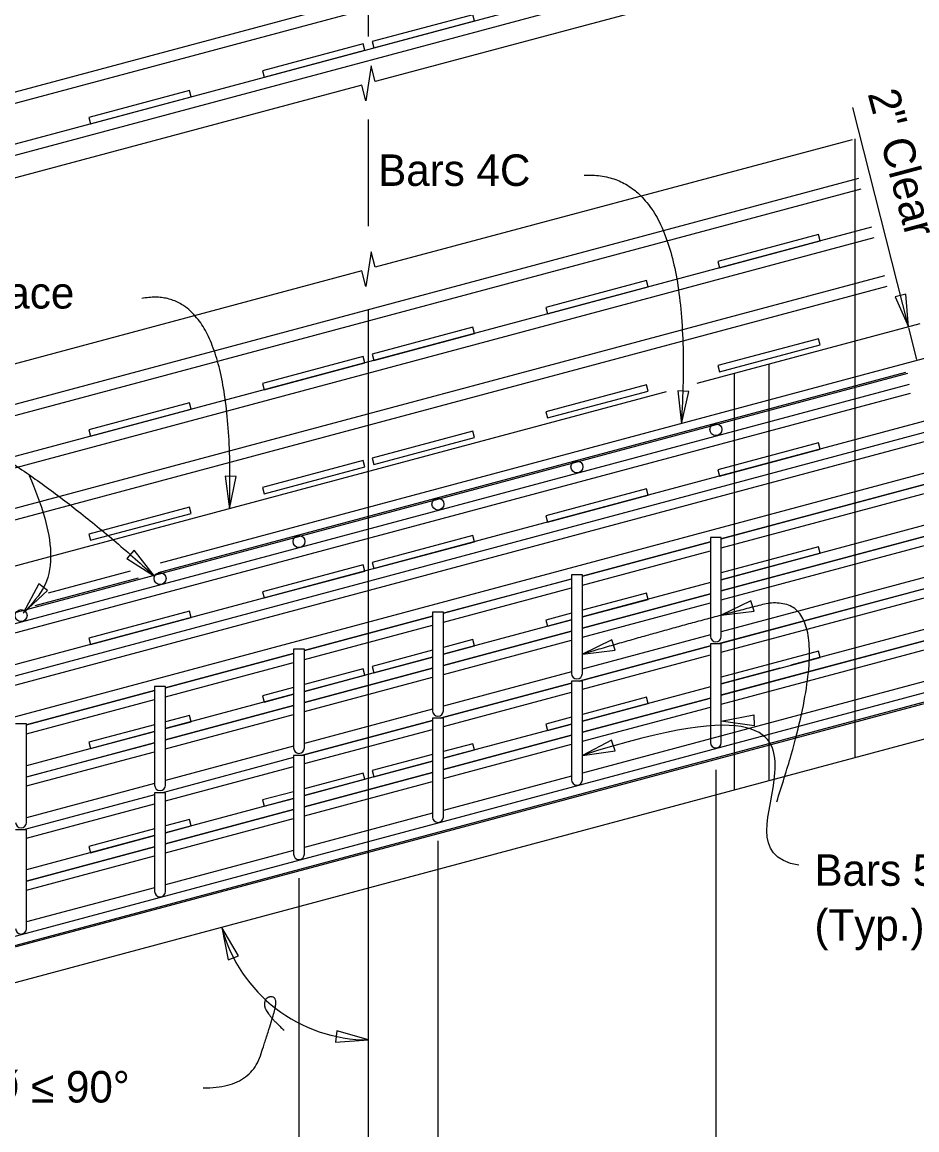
# Model space of a CAD drawing. Extents: x 120700.3 to 120754.4, y 120608.4 to 120631.3.
# Drawn here: x 120723.33 to 120727.62, y 120614.68 to 120620 of the extents above; entities that cross this region are included whole.
import ezdxf

# ---------------------------------------------------------------- set-up
doc = ezdxf.new("R2010")
doc.units = 0
for name, color, linetype in [('BeamConc', 7, 'Continuous'), ('BeamConc_h', 7, 'Continuous'), ('CL_Major', 7, 'Continuous'), ('Dimension', 7, 'Continuous'), ('Miscellaneous', 7, 'Continuous'), ('Rebar', 7, 'Continuous'), ('Rebar_h', 7, 'Continuous'), ('TextStructures', 7, 'Continuous')]:
    doc.layers.add(name, color=color, linetype=linetype)

msp = doc.modelspace()

# ---------------------------------------------------------------- linework, layer by layer
at = {"layer": 'BeamConc'}
for p, q in [((120727.6329, 120618.5474), (120726.5616, 120618.2603)), ((120726.4154, 120618.2211), (120722.3412, 120617.1295)), ((120729.1559, 120616.9555), (120721.7359, 120614.9673))]:
    msp.add_line(p, q, dxfattribs=at)
at = {"layer": 'BeamConc_h'}
msp.add_line((120727.3204, 120619.4351), (120727.3204, 120616.4636), dxfattribs=at)
at = {"layer": 'CL_Major'}
for p, q in [((120724.9871, 120619.9267), (120724.9871, 120621.4921)), ((120724.9871, 120619.0169), (120724.9871, 120619.5283)), ((120724.9871, 120613.7203), (120724.9871, 120618.6128))]:
    msp.add_line(p, q, dxfattribs=at)
at = {"layer": 'Dimension'}
for p, q in [((120727.5776, 120618.5325), (120727.3109, 120619.5857)), ((120727.6171, 120618.3763), (120727.5787, 120618.5283)), ((120726.6537, 120616.4065), (120726.6537, 120613.9805)), ((120725.3204, 120616.0658), (120725.3204, 120613.9805)), ((120724.6537, 120615.886), (120724.6537, 120613.9805))]:
    msp.add_line(p, q, dxfattribs=at)
for points in [[(120727.0943, 120620.2669), (120725.0196, 120619.7112), (120724.9996, 120619.786), (120724.9871, 120619.7024), (120724.9744, 120619.6188), (120724.9544, 120619.6937), (120722.9331, 120619.1523)], [(120727.3072, 120619.4316), (120725.0196, 120618.8189), (120724.9996, 120618.8936), (120724.9871, 120618.8101), (120724.9744, 120618.7265), (120724.9544, 120618.8014), (120722.9331, 120618.2599)]]:
    msp.add_lwpolyline(points, dxfattribs=at)
for points in [[(120727.5776, 120618.5326), (120727.5649, 120618.6905), (120727.5136, 120618.6775)], [(120726.4882, 120618.068), (120726.5241, 120618.2223), (120726.4713, 120618.2255)], [(120724.3207, 120617.6598), (120724.3517, 120617.8152), (120724.2988, 120617.8167)], [(120723.9611, 120617.336), (120723.8635, 120617.4607), (120723.8279, 120617.4216)], [(120723.3308, 120617.159), (120723.447, 120617.2667), (120723.4051, 120617.2989)], [(120726.6798, 120617.1484), (120726.837, 120617.1676), (120726.8219, 120617.2183)], [(120726.0131, 120616.9612), (120726.1704, 120616.9804), (120726.1553, 120617.0311)], [(120726.6798, 120616.6401), (120726.8352, 120616.671), (120726.8367, 120616.6181)], [(120726.0131, 120616.4754), (120726.1699, 120616.498), (120726.1537, 120616.5484)], [(120724.283, 120615.6497), (120724.3143, 120615.4949), (120724.364, 120615.5141)], [(120724.9871, 120615.1094), (120724.8352, 120615.1526), (120724.8295, 120615.0995)]]:
    msp.add_lwpolyline(points, close=True, dxfattribs=at)
msp.add_arc((120724.9871, 120615.8384), 0.7289, 195, 270, dxfattribs=at)
for points, degree in [([(120726.0213, 120619.2608), (120726.5627, 120619.2891), (120726.4882, 120618.0681)], 2), ([(120724.3207, 120617.6599), (120724.3524, 120618.754), (120723.8998, 120618.6691)], 2), ([(120722.026, 120618.2931), (120722.8238, 120618.3724), (120723.9611, 120617.336)], 2), ([(120726.9456, 120616.2534), (120727.2942, 120617.3053), (120726.4437, 120617.0895), (120726.0131, 120616.9613)], 2), ([(120727.0524, 120615.9478), (120726.8106, 120615.987), (120727.0349, 120616.4167), (120726.8673, 120616.7498), (120726.0131, 120616.4755)], 3), ([(120724.1946, 120614.8794), (120724.4171, 120614.877), (120724.5224, 120615.1961), (120724.5531, 120615.3162), (120724.4881, 120615.3162), (120724.4881, 120615.2411), (120724.5822, 120615.1561)], 2)]:
    msp.add_open_spline(points, degree=degree, dxfattribs=at)
msp.add_spline([(120723.3596, 120617.8193), (120723.4342, 120617.6139), (120723.4342, 120617.2934), (120723.3308, 120617.159)], degree=3, dxfattribs=at)
at = {"layer": 'Miscellaneous'}
for p, q in [((120726.9079, 120618.3531), (120726.9079, 120616.3531)), ((120726.7412, 120618.3084), (120726.7412, 120616.3084))]:
    msp.add_line(p, q, dxfattribs=at)
at = {"layer": 'Rebar'}
for p, q in [((120728.1236, 120618.5063), (120723.9872, 120617.3979)), ((120729.0388, 120618.3971), (120720.9246, 120616.2229)), ((120720.9354, 120616.1826), (120729.0496, 120618.3568)), ((120723.9797, 120617.3542), (120727.5656, 120618.3151)), ((120727.5804, 120618.2563), (120720.9246, 120616.4729)), ((120720.9354, 120616.4326), (120727.5878, 120618.2152)), ((120729.0388, 120618.1471), (120726.6798, 120617.515)), ((120726.6798, 120617.4719), (120729.0496, 120618.1068)), ((120729.0388, 120617.8971), (120726.6798, 120617.265)), ((120726.6798, 120617.2219), (120729.0496, 120617.8568)), ((120729.0388, 120617.6471), (120726.6652, 120617.0111)), ((120726.6798, 120616.9719), (120729.0496, 120617.6068)), ((120726.6277, 120617.501), (120726.0131, 120617.3364)), ((120726.6277, 120617.5211), (120726.6277, 120617.0471)), ((120726.6798, 120617.5211), (120726.6277, 120617.5211)), ((120726.6798, 120617.0471), (120726.6798, 120617.5211)), ((120726.0131, 120617.2932), (120726.6277, 120617.4579)), ((120729.0388, 120617.3971), (120726.6825, 120616.7657)), ((120723.3881, 120617.1957), (120723.8839, 120617.3286)), ((120723.8443, 120617.3596), (120723.4509, 120617.2542)), ((120725.961, 120617.3425), (120725.961, 120616.8685)), ((120726.0131, 120617.3425), (120725.961, 120617.3425)), ((120726.0131, 120616.8685), (120726.0131, 120617.3425)), ((120726.6798, 120616.7219), (120729.0496, 120617.3568)), ((120725.961, 120617.3224), (120725.3464, 120617.1577)), ((120725.3464, 120617.1146), (120725.961, 120617.2793)), ((120726.6277, 120617.251), (120726.0131, 120617.0864)), ((120725.2944, 120617.1638), (120725.2944, 120616.6898)), ((120725.3464, 120617.1638), (120725.2944, 120617.1638)), ((120725.3464, 120616.6898), (120725.3464, 120617.1638)), ((120726.0131, 120617.0432), (120726.6277, 120617.2079)), ((120725.2944, 120617.1438), (120724.6798, 120616.9791)), ((120724.6798, 120616.936), (120725.2944, 120617.1006)), ((120725.961, 120617.0724), (120725.3464, 120616.9077)), ((120725.3464, 120616.8646), (120725.961, 120617.0293)), ((120726.6277, 120617.0111), (120726.6277, 120616.5371)), ((120726.6798, 120617.0111), (120726.6277, 120617.0111)), ((120726.6798, 120616.5371), (120726.6798, 120617.0111)), ((120724.6277, 120616.9651), (120724.0131, 120616.8005)), ((120724.6277, 120616.9852), (120724.6277, 120616.5112)), ((120724.6798, 120616.9852), (120724.6277, 120616.9852)), ((120724.6798, 120616.5112), (120724.6798, 120616.9852)), ((120726.6277, 120617.001), (120725.9986, 120616.8325)), ((120726.0131, 120616.7932), (120726.6277, 120616.9579)), ((120724.0131, 120616.7573), (120724.6277, 120616.922)), ((120721.9785, 120615.2049), (120728.1035, 120616.8461)), ((120725.2944, 120616.8938), (120724.6798, 120616.7291)), ((120724.6798, 120616.686), (120725.2944, 120616.8506)), ((120727.8702, 120616.834), (120720.9246, 120614.9729)), ((120720.9354, 120614.9326), (120727.8827, 120616.7942)), ((120723.961, 120616.8066), (120723.961, 120616.3326)), ((120724.0131, 120616.8066), (120723.961, 120616.8066)), ((120724.0131, 120616.3326), (120724.0131, 120616.8066)), ((120725.961, 120616.8224), (120725.3317, 120616.6538)), ((120725.961, 120616.8325), (120725.961, 120616.3585)), ((120726.0131, 120616.8325), (120725.961, 120616.8325)), ((120726.0131, 120616.3585), (120726.0131, 120616.8325)), ((120723.961, 120616.7865), (120723.3464, 120616.6218)), ((120723.3464, 120616.5787), (120723.961, 120616.7434)), ((120725.3464, 120616.6146), (120725.961, 120616.7793)), ((120726.6277, 120616.751), (120726.0131, 120616.5864)), ((120724.6277, 120616.7151), (120724.0131, 120616.5505)), ((120726.0131, 120616.5432), (120726.6277, 120616.7079)), ((120724.0131, 120616.5073), (120724.6277, 120616.672)), ((120725.2944, 120616.6438), (120724.6652, 120616.4752)), ((120725.2944, 120616.6538), (120725.2944, 120616.1798)), ((120725.3464, 120616.6538), (120725.2944, 120616.6538)), ((120725.3464, 120616.1798), (120725.3464, 120616.6538)), ((120723.3464, 120616.6279), (120723.2944, 120616.6279)), ((120723.3464, 120616.1539), (120723.3464, 120616.6279)), ((120724.6798, 120616.436), (120725.2944, 120616.6006)), ((120723.961, 120616.5365), (120723.3464, 120616.3718)), ((120725.961, 120616.5724), (120725.3464, 120616.4077)), ((120725.3464, 120616.3646), (120725.961, 120616.5293)), ((120723.3464, 120616.3287), (120723.961, 120616.4934)), ((120724.6277, 120616.4752), (120724.6277, 120616.0012)), ((120724.6798, 120616.4752), (120724.6277, 120616.4752)), ((120724.6798, 120616.0012), (120724.6798, 120616.4752)), ((120724.6277, 120616.4651), (120723.9986, 120616.2966)), ((120724.0131, 120616.2573), (120724.6277, 120616.422)), ((120725.2944, 120616.3938), (120724.6798, 120616.2291)), ((120724.6798, 120616.186), (120725.2944, 120616.3506)), ((120723.961, 120616.2865), (120723.3317, 120616.1179)), ((120723.961, 120616.2966), (120723.961, 120615.8226)), ((120724.0131, 120616.2966), (120723.961, 120616.2966)), ((120724.0131, 120615.8226), (120724.0131, 120616.2966)), ((120723.3464, 120616.0787), (120723.961, 120616.2434)), ((120724.6277, 120616.2151), (120724.0131, 120616.0505)), ((120724.0131, 120616.0073), (120724.6277, 120616.172)), ((120723.3464, 120616.1179), (120723.2944, 120616.1179)), ((120723.3464, 120615.6439), (120723.3464, 120616.1179)), ((120723.961, 120616.0365), (120723.3464, 120615.8718)), ((120723.3464, 120615.8287), (120723.961, 120615.9934))]:
    msp.add_line(p, q, dxfattribs=at)
for points in [[(120725.0122, 120619.8721), (120725.4952, 120620.0015), (120725.4871, 120620.0317), (120725.0041, 120619.9023)], [(120724.4871, 120619.7314), (120724.97, 120619.8608), (120724.9619, 120619.891), (120724.479, 120619.7616)], [(120723.6537, 120619.5081), (120724.1367, 120619.6375), (120724.1286, 120619.6677), (120723.6457, 120619.5383)], [(120726.6708, 120618.8165), (120727.1537, 120618.9459), (120727.1457, 120618.9761), (120726.6627, 120618.8467)], [(120725.8455, 120618.5954), (120726.3285, 120618.7248), (120726.3204, 120618.755), (120725.8374, 120618.6256)], [(120725.0122, 120618.3721), (120725.4952, 120618.5015), (120725.4871, 120618.5317), (120725.0041, 120618.4023)], [(120726.6708, 120618.3165), (120727.1537, 120618.4459), (120727.1457, 120618.4761), (120726.6627, 120618.3467)], [(120724.4871, 120618.2314), (120724.97, 120618.3608), (120724.9619, 120618.391), (120724.479, 120618.2616)], [(120725.8455, 120618.0954), (120726.3285, 120618.2248), (120726.3204, 120618.255), (120725.8374, 120618.1256)], [(120723.6537, 120618.0081), (120724.1367, 120618.1375), (120724.1286, 120618.1677), (120723.6457, 120618.0383)], [(120725.0122, 120617.8721), (120725.4952, 120618.0015), (120725.4871, 120618.0317), (120725.0041, 120617.9023)], [(120726.6708, 120617.8165), (120727.1537, 120617.9459), (120727.1457, 120617.9761), (120726.6627, 120617.8467)], [(120724.4871, 120617.7314), (120724.97, 120617.8608), (120724.9619, 120617.891), (120724.479, 120617.7616)], [(120725.8455, 120617.5954), (120726.3285, 120617.7248), (120726.3204, 120617.755), (120725.8374, 120617.6256)], [(120723.6537, 120617.5081), (120724.1367, 120617.6375), (120724.1286, 120617.6677), (120723.6457, 120617.5383)], [(120725.0122, 120617.3721), (120725.4952, 120617.5015), (120725.4871, 120617.5317), (120725.0041, 120617.4023)], [(120724.4871, 120617.2314), (120724.97, 120617.3608), (120724.9619, 120617.391), (120724.479, 120617.2616)], [(120723.6537, 120617.0081), (120724.1367, 120617.1375), (120724.1286, 120617.1677), (120723.6457, 120617.0383)]]:
    msp.add_lwpolyline(points, close=True, dxfattribs=at)
for points in [[(120726.6798, 120617.2651), (120729.0283, 120617.8944), (120729.0149, 120617.9446), (120728.2579, 120617.7418)], [(120726.6798, 120617.3189), (120727.1537, 120617.4459), (120727.1457, 120617.4761), (120726.6798, 120617.3513)], [(120726.0131, 120617.1403), (120726.3285, 120617.2248), (120726.3204, 120617.255), (120726.0131, 120617.1726)], [(120725.961, 120617.1587), (120725.8374, 120617.1256), (120725.8455, 120617.0954), (120725.961, 120617.1263)], [(120725.3464, 120616.9616), (120725.4952, 120617.0015), (120725.4871, 120617.0317), (120725.3464, 120616.994)], [(120725.2944, 120616.98), (120725.0041, 120616.9023), (120725.0122, 120616.8721), (120725.2944, 120616.9477)], [(120726.6798, 120616.8189), (120727.1537, 120616.9459), (120727.1457, 120616.9761), (120726.6798, 120616.8513)], [(120724.6798, 120616.783), (120724.97, 120616.8608), (120724.9619, 120616.891), (120724.6798, 120616.8154)], [(120724.6277, 120616.8014), (120724.479, 120616.7616), (120724.4871, 120616.7314), (120724.6277, 120616.7691)], [(120726.0131, 120616.6403), (120726.3285, 120616.7248), (120726.3204, 120616.755), (120726.0131, 120616.6726)], [(120724.0131, 120616.6044), (120724.1367, 120616.6375), (120724.1286, 120616.6677), (120724.0131, 120616.6367)], [(120725.961, 120616.6587), (120725.8374, 120616.6256), (120725.8455, 120616.5954), (120725.961, 120616.6263)], [(120723.961, 120616.6228), (120723.6457, 120616.5383), (120723.6537, 120616.5081), (120723.961, 120616.5904)], [(120725.3464, 120616.4616), (120725.4952, 120616.5015), (120725.4871, 120616.5317), (120725.3464, 120616.494)], [(120725.2944, 120616.48), (120725.0041, 120616.4023), (120725.0122, 120616.3721), (120725.2944, 120616.4477)], [(120724.6798, 120616.283), (120724.97, 120616.3608), (120724.9619, 120616.391), (120724.6798, 120616.3154)], [(120724.6277, 120616.3014), (120724.479, 120616.2616), (120724.4871, 120616.2314), (120724.6277, 120616.2691)], [(120724.0131, 120616.1044), (120724.1367, 120616.1375), (120724.1286, 120616.1677), (120724.0131, 120616.1367)], [(120723.961, 120616.1228), (120723.6457, 120616.0383), (120723.6537, 120616.0081), (120723.961, 120616.0904)]]:
    msp.add_lwpolyline(points, dxfattribs=at)
for centre in [(120726.6537, 120618.0396), (120725.9871, 120617.8609), (120725.3204, 120617.6821), (120724.6537, 120617.5022), (120723.9871, 120617.3246), (120723.3204, 120617.1468)]:
    msp.add_circle(centre, 0.0287, dxfattribs=at)
for centre in [(120726.6537, 120617.0471), (120725.9871, 120616.8685), (120725.3204, 120616.6898), (120726.6537, 120616.5371), (120724.6537, 120616.5112), (120723.9871, 120616.3326), (120725.9871, 120616.3585), (120723.3204, 120616.1539), (120725.3204, 120616.1798), (120724.6537, 120616.0012), (120723.9871, 120615.8226), (120723.3204, 120615.6439)]:
    msp.add_arc(centre, 0.026, 179.9998, 359.9995, dxfattribs=at)
at = {"layer": 'Rebar_h'}
for p, q in [((120727.3373, 120619.2451), (120721.9114, 120617.7912)), ((120721.5232, 120617.6333), (120727.3508, 120619.1949)), ((120727.3998, 120619.0119), (120721.9114, 120617.5412)), ((120721.5232, 120617.3833), (120727.4133, 120618.9616)), ((120727.4623, 120618.7786), (120721.9114, 120617.2912)), ((120721.5232, 120617.1333), (120727.4758, 120618.7284)), ((120727.5735, 120618.3084), (120720.936, 120616.5299)), ((120728.2114, 120616.9793), (120726.0131, 120616.3903))]:
    msp.add_line(p, q, dxfattribs=at)
for points in [[(120729.0149, 120621.1946), (120720.936, 120619.0299), (120720.9494, 120618.9796), (120729.0283, 120621.1444)], [(120729.0149, 120620.9446), (120720.936, 120618.7799), (120720.9494, 120618.7296), (120729.0283, 120620.8944)]]:
    msp.add_lwpolyline(points, close=True, dxfattribs=at)
for points in [[(120728.2163, 120618.2306), (120721.7579, 120616.5001)], [(120726.6798, 120617.5151), (120729.0283, 120618.1444), (120729.0149, 120618.1946), (120728.2579, 120617.9918)], [(120728.2163, 120617.9806), (120721.7579, 120616.2501)], [(120728.2163, 120617.7306), (120726.6798, 120617.3189)], [(120726.6798, 120617.0151), (120729.0283, 120617.6444), (120729.0149, 120617.6946), (120728.2579, 120617.4918)], [(120726.0131, 120617.3364), (120726.6277, 120617.5011)], [(120728.2163, 120617.4806), (120726.6798, 120617.0689)], [(120726.6798, 120616.7651), (120729.0283, 120617.3944), (120729.0149, 120617.4446), (120728.2579, 120617.2418)], [(120725.3464, 120617.1578), (120725.961, 120617.3225)], [(120726.6277, 120617.305), (120726.0131, 120617.1403)], [(120726.0131, 120617.0864), (120726.6277, 120617.2511)], [(120728.2163, 120617.2306), (120727.0131, 120616.9082)], [(120724.6798, 120616.9792), (120725.2944, 120617.1438)], [(120725.961, 120617.1263), (120725.3464, 120616.9616)], [(120725.3464, 120616.9078), (120725.961, 120617.0725)], [(120726.6277, 120617.055), (120726.0131, 120616.8903)], [(120724.0131, 120616.8005), (120724.6277, 120616.9652)], [(120725.9983, 120616.8325), (120726.6277, 120617.0011)], [(120725.2944, 120616.9477), (120724.6798, 120616.783)], [(120724.6798, 120616.7292), (120725.2944, 120616.8938)], [(120725.961, 120616.8763), (120725.3464, 120616.7116)], [(120726.961, 120616.8943), (120726.6798, 120616.8189)], [(120725.3314, 120616.6538), (120725.961, 120616.8225)], [(120726.6277, 120616.805), (120726.0131, 120616.6403)], [(120723.3464, 120616.6219), (120723.961, 120616.7866)], [(120724.6277, 120616.7691), (120724.0131, 120616.6044)], [(120726.0131, 120616.5864), (120726.6277, 120616.7511)], [(120724.0131, 120616.5505), (120724.6277, 120616.7152)], [(120725.2944, 120616.6977), (120724.6798, 120616.533)], [(120724.665, 120616.4752), (120725.2944, 120616.6438)], [(120723.961, 120616.5904), (120723.3464, 120616.4258)], [(120725.961, 120616.6263), (120725.3464, 120616.4616)], [(120723.3464, 120616.3719), (120723.961, 120616.5366)], [(120725.3464, 120616.4078), (120725.961, 120616.5725)], [(120724.6277, 120616.5191), (120724.0131, 120616.3544)], [(120725.2944, 120616.4477), (120724.6798, 120616.283)], [(120724.6798, 120616.2292), (120725.2944, 120616.3938)], [(120725.961, 120616.3763), (120725.3464, 120616.2116)], [(120723.961, 120616.3404), (120723.3464, 120616.1758)], [(120724.6277, 120616.2691), (120724.0131, 120616.1044)], [(120724.0131, 120616.0505), (120724.6277, 120616.2152)], [(120725.2944, 120616.1977), (120724.6798, 120616.033)], [(120723.961, 120616.0904), (120723.3464, 120615.9258)], [(120723.3464, 120615.8719), (120723.961, 120616.0366)], [(120724.6277, 120616.0191), (120724.0131, 120615.8544)], [(120723.961, 120615.8404), (120723.3464, 120615.6758)]]:
    msp.add_lwpolyline(points, dxfattribs=at)

# ---------------------------------------------------------------- texts
at = {"layer": 'Dimension'}
for s, p in [('Bars 5E ', (120727.1267, 120615.8496)), ('(Typ.)', (120727.1267, 120615.5856))]:
    msp.add_text(s, height=0.1512, dxfattribs=at).set_placement(p)
at = {"layer": 'TextStructures'}
msp.add_text('2" Clear', height=0.1512, rotation=285, dxfattribs=at).set_placement((120727.381, 120619.6526))
for s, p in [('Bars 4C', (120725.0335, 120619.2096)), ('Void Face', (120722.6655, 120618.6208)), ('75° ≤ Ø ≤ 90°', (120722.6262, 120614.809))]:
    msp.add_text(s, height=0.1512, dxfattribs=at).set_placement(p)

doc.saveas('drawing.dxf')
